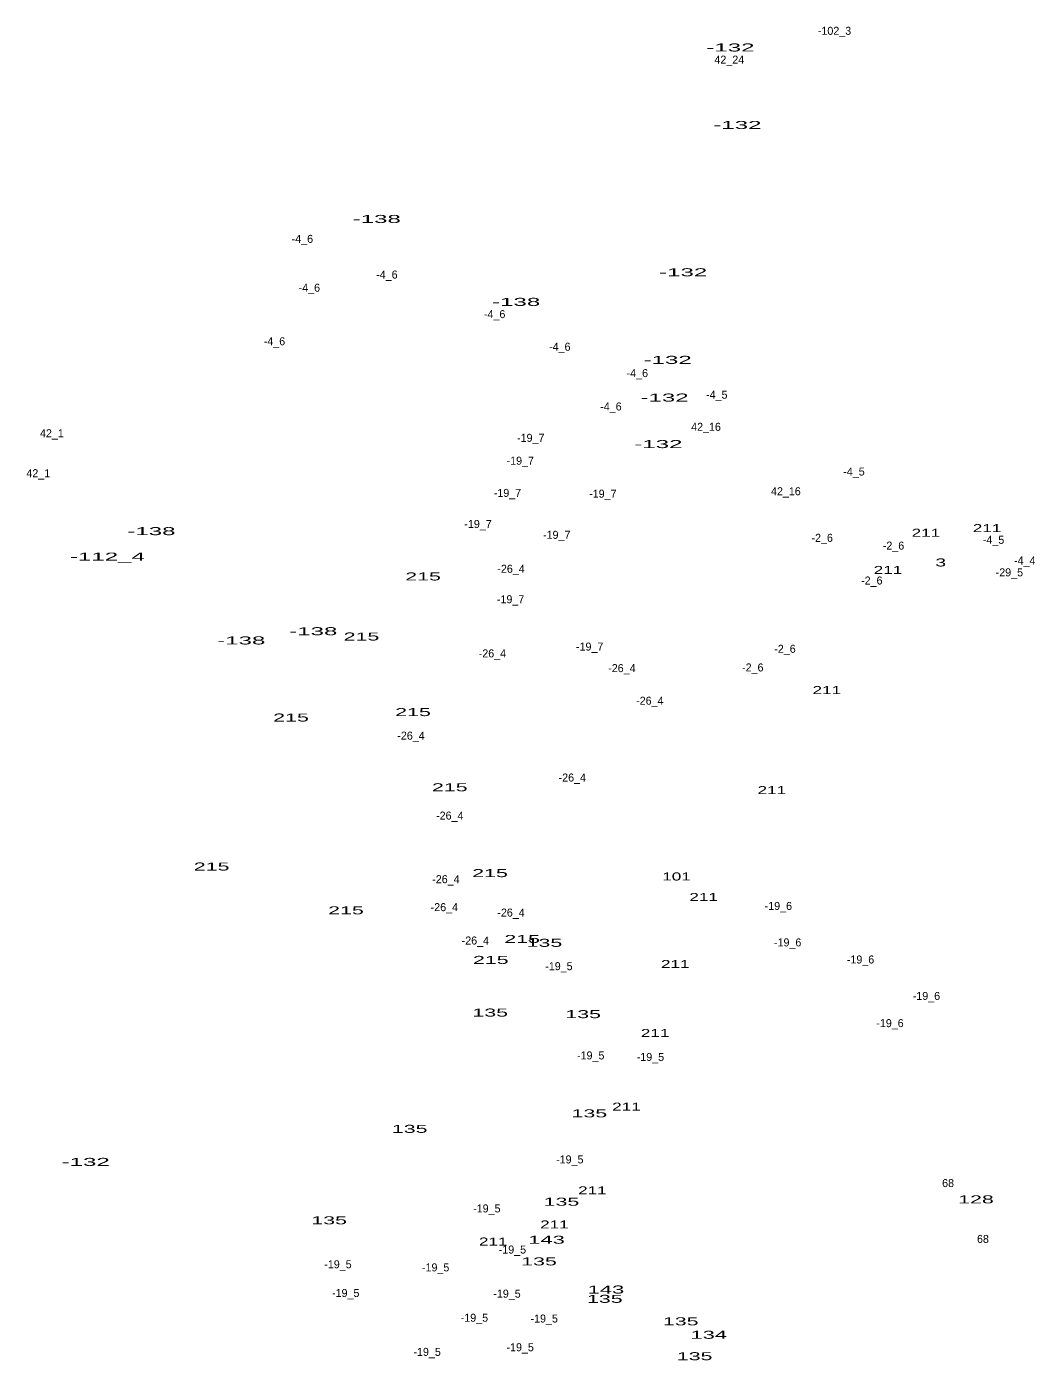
# Model space of a CAD drawing. Extents: x -656096 to -652763, y -1002270 to -998958.
# Drawn here: x -655411 to -654910, y -1001392 to -1000726 of the extents above; entities that cross this region are included whole.
import ezdxf
from ezdxf.enums import TextEntityAlignment as Align

# ---------------------------------------------------------------- set-up
doc = ezdxf.new("R2010")
doc.units = 0
doc.header["$LTSCALE"] = 1.6
doc.layers.add('24', color=7, linetype='Continuous')

msp = doc.modelspace()

# ---------------------------------------------------------------- texts
at = {"layer": '24'}
for s, p in [('-102_3', (-655007.5, -1000729.58)), ('42_24', (-655060.114, -1000743.99)), ('-4_6', (-655273.613, -1000833.56)), ('-4_6', (-655231.353, -1000851.41)), ('-4_6', (-655270.123, -1000858)), ('-4_6', (-655177.463, -1000871.19)), ('-4_6', (-655287.573, -1000884.76)), ('-4_6', (-655144.893, -1000887.48)), ('-4_6', (-655106.113, -1000900.67)), ('-4_5', (-655066.388, -1000911.45)), ('-4_6', (-655119.303, -1000917.35)), ('42_1', (-655398.883, -1000930.73)), ('-19_7', (-655159.417, -1000933.02)), ('42_16', (-655071.768, -1000927.52)), ('-19_7', (-655164.647, -1000944.46)), ('42_1', (-655405.673, -1000950.7)), ('-4_5', (-654997.758, -1000949.85)), ('42_16', (-655031.828, -1000959.72)), ('-19_7', (-655171.047, -1000960.55)), ('-19_7', (-655123.357, -1000960.94)), ('-19_7', (-655185.777, -1000976.07)), ('-19_7', (-655146.427, -1000981.5)), ('-2_6', (-655013.669, -1000983)), ('-4_5', (-654927.968, -1000983.98)), ('-2_6', (-654977.999, -1000986.88)), ('-26_4', (-655169.272, -1000998.47)), ('-4_4', (-654912.362, -1000994.33)), ('-2_6', (-654988.859, -1001004.34)), ('-29_5', (-654920.068, -1001000.25)), ('-19_7', (-655169.497, -1001013.69)), ('-19_7', (-655129.947, -1001037.35)), ('-2_6', (-655032.279, -1001038.47)), ('-26_4', (-655178.582, -1001040.75)), ('-26_4', (-655113.832, -1001048.12)), ('-2_6', (-655048.379, -1001047.78)), ('-26_4', (-655099.872, -1001064.41)), ('-26_4', (-655219.292, -1001081.87)), ('-26_4', (-655138.642, -1001102.81)), ('-26_4', (-655199.912, -1001121.82)), ('-26_4', (-655201.842, -1001153.62)), ('-26_4', (-655202.622, -1001167.59)), ('-26_4', (-655169.272, -1001170.3)), ('-19_6', (-655035.587, -1001166.98)), ('-26_4', (-655187.112, -1001184.27)), ('-19_6', (-655030.937, -1001185.21)), ('-19_5', (-655145.322, -1001197.09)), ('-19_6', (-654994.487, -1001193.74)), ('-19_6', (-654961.537, -1001211.97)), ('-19_6', (-654979.757, -1001225.55)), ('-19_5', (-655129.422, -1001241.69)), ('-19_5', (-655099.562, -1001242.47)), ('-19_5', (-655139.892, -1001293.67)), ('68', (-654950.723, -1001305.49)), ('-19_5', (-655181.382, -1001318.16)), ('68', (-654933.273, -1001333.42)), ('-19_5', (-655168.582, -1001338.72)), ('-19_5', (-655255.822, -1001346.09)), ('-19_5', (-655206.972, -1001347.64)), ('-19_5', (-655251.942, -1001360.44)), ('-19_5', (-655171.292, -1001360.77)), ('-19_5', (-655187.582, -1001372.8)), ('-19_5', (-655152.682, -1001373.19)), ('-19_5', (-655211.232, -1001389.86)), ('-19_5', (-655164.702, -1001387.54))]:
    msp.add_text(s, height=4, dxfattribs=at).set_placement(p, align=Align.CENTER)
for s, width, p in [('-132', 2.25, (-655059.571, -1000737.92)), ('-132', 2.25, (-655056.081, -1000776.66)), ('-138', 2.25, (-655236.421, -1000823.62)), ('-132', 2.25, (-655083.191, -1000850.27)), ('-138', 2.25, (-655166.711, -1000865.07)), ('-132', 2.25, (-655090.941, -1000894.05)), ('-132', 2.25, (-655092.491, -1000912.9)), ('-132', 2.25, (-655095.591, -1000936.14)), ('-138', 2.25, (-655349.111, -1000979.66)), ('211', 1.6, (-654931.204, -1000978.13)), ('211', 1.6, (-654961.794, -1000980.46)), ('-112_4', 2.25, (-655371.123, -1000992.39)), ('211', 1.6, (-654980.774, -1000999.05)), ('3', 1.8, (-654954.391, -1000995.3)), ('215', 2, (-655213.257, -1001002.3)), ('-138', 2.25, (-655268.171, -1001029.67)), ('215', 2, (-655244.047, -1001032.32)), ('-138', 2.25, (-655304.191, -1001034.28)), ('211', 1.6, (-655011.364, -1001059.1)), ('215', 2, (-655279.287, -1001072.81)), ('215', 2, (-655218.287, -1001070.09)), ('215', 2, (-655199.897, -1001107.67)), ('211', 1.6, (-655038.864, -1001109.08)), ('215', 2, (-655318.997, -1001147.28)), ('215', 2, (-655179.777, -1001150.57)), ('101', 1.6, (-655086.52, -1001152.25)), ('211', 1.6, (-655072.944, -1001162.51)), ('215', 2, (-655251.807, -1001169.17)), ('215', 2, (-655163.707, -1001183.5)), ('135', 2, (-655152.577, -1001185.42)), ('215', 2, (-655179.387, -1001193.96)), ('211', 1.6, (-655087.154, -1001196.01)), ('135', 2, (-655179.677, -1001220.28)), ('135', 2, (-655133.207, -1001221.06)), ('211', 1.6, (-655097.224, -1001230.49)), ('135', 2, (-655130.107, -1001270.65)), ('211', 1.6, (-655111.554, -1001267.3)), ('135', 2, (-655219.957, -1001278.39)), ('-132', 2.25, (-655381.971, -1001294.92)), ('211', 1.6, (-655128.594, -1001309.14)), ('135', 2, (-655144.057, -1001314.81)), ('128', 2, (-654936.767, -1001313.64)), ('135', 2, (-655260.237, -1001324.11)), ('211', 1.6, (-655147.574, -1001326.18)), ('211', 1.6, (-655178.164, -1001334.7)), ('143', 2.05, (-655151.523, -1001333.81)), ('135', 2, (-655155.287, -1001344.64)), ('143', 2.05, (-655121.803, -1001358.71)), ('135', 2, (-655122.367, -1001363.36)), ('135', 2, (-655084.417, -1001374.6)), ('134', 2.05, (-655070.413, -1001381.31)), ('135', 2, (-655077.447, -1001392.03))]:
    msp.add_text(s, height=4, dxfattribs=dict(at, width=width)).set_placement(p, align=Align.CENTER)

doc.saveas('drawing.dxf')
